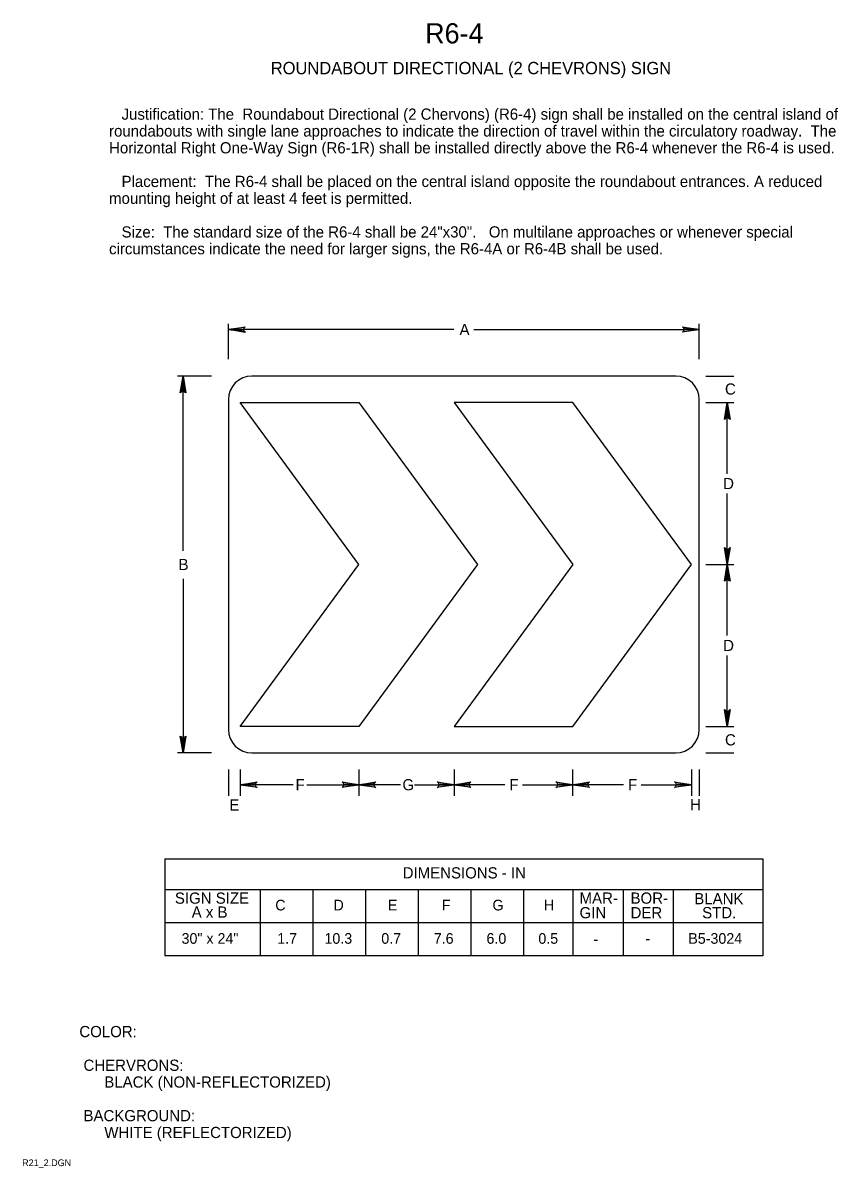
# Model space of a CAD drawing. Extents: x 0.013 to 0.194, y 0.004 to 0.259.
import ezdxf

# ---------------------------------------------------------------- set-up
doc = ezdxf.new("R2010")
doc.units = 0
for name, color, linetype in [('1', 7, 'Continuous'), ('2', 7, 'Continuous'), ('3', 7, 'Continuous')]:
    doc.layers.add(name, color=color, linetype=linetype)

# ---------------------------------------------------------------- blocks, each defined once
blk = doc.blocks.new('RARROW')
at = {"layer": '3'}
for p, q in [((-2.156, 0.285), (-2.2665, 0.384625)), ((-2.2665, 0.384625), (0, 0)), ((0, 0), (-2.2665, -0.379125)), ((-2.156, 0.285), (-2.075625, 0.12075)), ((0, 0), (-2.156, 0.285)), ((-2.14975, -0.2705), (0, 0)), ((-2.075625, 0.12075), (0, 0)), ((0, 0), (-2.074, -0.108)), ((-2.2665, -0.379125), (-2.14975, -0.2705)), ((-2.074, -0.108), (-2.14975, -0.2705))]:
    blk.add_line(p, q, dxfattribs=at)

msp = doc.modelspace()

# ---------------------------------------------------------------- linework, layer by layer
at = {"layer": '3'}
for p, q in [((0.05838, 0.18423), (0.05838, 0.1921)), ((0.16337, 0.18423), (0.16337, 0.1921)), ((0.10867, 0.19085), (0.05838, 0.19085)), ((0.11308, 0.19085), (0.16337, 0.19085)), ((0.05462, 0.18048), (0.047, 0.18048)), ((0.04825, 0.14154), (0.04825, 0.18048)), ((0.15813, 0.18048), (0.06363, 0.18048)), ((0.16487, 0.18048), (0.17112, 0.18048)), ((0.05838, 0.17523), (0.05838, 0.10173)), ((0.08747, 0.13848), (0.061, 0.17457)), ((0.061, 0.17457), (0.08747, 0.17457)), ((0.16337, 0.10173), (0.16337, 0.17523)), ((0.16487, 0.17457), (0.17112, 0.17457)), ((0.16964, 0.15872), (0.16964, 0.17457)), ((0.16964, 0.13848), (0.16964, 0.15432)), ((0.061, 0.10238), (0.08747, 0.13848)), ((0.16487, 0.13848), (0.17112, 0.13848)), ((0.16964, 0.12262), (0.16964, 0.13848)), ((0.04825, 0.13525), (0.04825, 0.09648)), ((0.16964, 0.10238), (0.16964, 0.11823)), ((0.16487, 0.10238), (0.17112, 0.10238)), ((0.05462, 0.09648), (0.047, 0.09648)), ((0.06363, 0.09648), (0.15813, 0.09648)), ((0.16487, 0.09648), (0.17112, 0.09648)), ((0.05838, 0.09278), (0.05838, 0.08695)), ((0.061, 0.09278), (0.061, 0.08695)), ((0.08747, 0.09278), (0.08747, 0.08695)), ((0.10869, 0.09278), (0.10869, 0.08695)), ((0.13516, 0.08695), (0.13516, 0.09278)), ((0.16162, 0.09278), (0.16162, 0.08695)), ((0.16337, 0.09278), (0.16337, 0.08695)), ((0.07283, 0.08939), (0.06112, 0.08939)), ((0.0759, 0.08939), (0.08747, 0.08939)), ((0.09675, 0.08939), (0.08759, 0.08939)), ((0.09984, 0.08939), (0.10869, 0.08939)), ((0.12005, 0.08939), (0.10869, 0.08939)), ((0.12394, 0.08939), (0.13516, 0.08939)), ((0.14652, 0.08939), (0.13516, 0.08939)), ((0.15041, 0.08939), (0.16162, 0.08939)), ((0.04419, 0.07287), (0.17756, 0.07287)), ((0.04419, 0.07287), (0.04419, 0.05125)), ((0.17756, 0.07287), (0.17756, 0.05125)), ((0.17756, 0.066), (0.04419, 0.066)), ((0.06544, 0.066), (0.06544, 0.05125)), ((0.07719, 0.066), (0.07719, 0.05125)), ((0.08894, 0.066), (0.08894, 0.05125)), ((0.10069, 0.066), (0.10069, 0.05125)), ((0.11244, 0.066), (0.11244, 0.05125)), ((0.12419, 0.066), (0.12419, 0.05125)), ((0.12419, 0.066), (0.12419, 0.05262)), ((0.1352, 0.066), (0.1352, 0.05125)), ((0.14644, 0.066), (0.14644, 0.05125)), ((0.15756, 0.066), (0.15756, 0.05125)), ((0.17756, 0.05862), (0.04419, 0.05862)), ((0.17756, 0.05125), (0.04419, 0.05125))]:
    msp.add_line(p, q, dxfattribs=at)
msp.add_lwpolyline([(0.08747, 0.17457), (0.11394, 0.13848), (0.08747, 0.10238), (0.061, 0.10238)], dxfattribs=at)
msp.add_lwpolyline([(0.13516, 0.17457), (0.10869, 0.17457), (0.13516, 0.13848), (0.10869, 0.10238), (0.13516, 0.10238), (0.16162, 0.13848)], close=True, dxfattribs=at)
for centre, start, end in [((0.06363, 0.17523), 90, 180), ((0.15813, 0.17523), 0, 90), ((0.06363, 0.10173), 180, 270), ((0.15813, 0.10173), 270, 0)]:
    msp.add_arc(centre, 0.00525, start, end, dxfattribs=at)

# ---------------------------------------------------------------- block references
at = {"layer": '3', "xscale": 0.0016545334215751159, "yscale": 0.0016366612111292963}
for p, rotation in [((0.05838, 0.19085), 180), ((0.04825, 0.18048), 90), ((0.16964, 0.17457), 90), ((0.16964, 0.13848), -90), ((0.16964, 0.13848), 90), ((0.16964, 0.10238), -90), ((0.04825, 0.09648), -90), ((0.061, 0.08939), 180), ((0.08747, 0.08939), 180), ((0.10869, 0.08939), 180), ((0.13516, 0.08939), 180)]:
    msp.add_blockref('RARROW', p, dxfattribs=dict(at, rotation=rotation))
for p in [(0.16337, 0.19085), (0.08747, 0.08939), (0.10869, 0.08939), (0.13516, 0.08939), (0.16162, 0.08939)]:
    msp.add_blockref('RARROW', p, dxfattribs=at)

# ---------------------------------------------------------------- texts
at = {"layer": '1'}
for s, height, p in [('R6-4', 0.0045, (0.10224, 0.25462)), ('ROUNDABOUT DIRECTIONAL (2 CHEVRONS) SIGN', 0.0027503, (0.06782, 0.24775)), ('COLOR:', 0.0025, (0.02513, 0.03312)), (' CHERVRONS:', 0.0024998, (0.02513, 0.02562)), ('      BLACK (NON-REFLECTORIZED)', 0.0024998, (0.02513, 0.02188)), (' BACKGROUND:', 0.0024998, (0.02513, 0.01438)), ('      WHITE (REFLECTORIZED)', 0.0024998, (0.02513, 0.01063)), ('R21_2.DGN', 0.0015, (0.01238, 0.00438))]:
    msp.add_text(s, height=height, dxfattribs=at).set_placement(p)
at = {"layer": '2'}
for s, height, p in [('   Justification: The  Roundabout Directional (2 Chervons) (R6-4) sign shall be installed on the central island of', 0.00249975, (0.03176, 0.23761)), ('roundabouts with single lane approaches to indicate the direction of travel within the circulatory roadway.  The ', 0.00249975, (0.03176, 0.23386)), ('Horizontal Right One-Way Sign (R6-1R) shall be installed directly above the R6-4 whenever the R6-4 is used.', 0.00249975, (0.03176, 0.23011)), ('   Placement:  The R6-4 shall be placed on the central island opposite the roundabout entrances. A reduced', 0.00249975, (0.03176, 0.22261)), ('mounting height of at least 4 feet is permitted.', 0.0024998, (0.03176, 0.21886)), ('   Size:  The standard size of the R6-4 shall be 24"x30".   On multilane approaches or whenever special ', 0.00249975, (0.03176, 0.21136)), ('circumstances indicate the need for larger signs, the R6-4A or R6-4B shall be used.', 0.0024998, (0.03176, 0.20761))]:
    msp.add_text(s, height=height, dxfattribs=at).set_placement(p)
at = {"layer": '3'}
for s, height, p in [('A', 0.0025, (0.10992, 0.1896)), ('C', 0.0025, (0.16912, 0.17634)), ('D', 0.0025, (0.16871, 0.15527)), ('B', 0.0025, (0.04725, 0.13723)), ('D', 0.0025, (0.16871, 0.11918)), ('C', 0.0025, (0.16912, 0.09814)), ('F', 0.0025, (0.07335, 0.08814)), ('G', 0.0025, (0.09719, 0.08814)), ('F', 0.0025, (0.12104, 0.08814)), ('F', 0.0025, (0.14751, 0.08814)), ('E', 0.0025, (0.05857, 0.08364)), ('H', 0.0025, (0.16136, 0.08371)), ('DIMENSIONS - IN', 0.0024998, (0.09724, 0.0685)), ('SIGN SIZE', 0.0025, (0.04644, 0.06287)), ('MAR-', 0.0025, (0.13669, 0.06287)), ('BOR-', 0.0025, (0.14806, 0.06287)), ('BLANK', 0.0025, (0.16227, 0.06275)), ('A x B', 0.0025, (0.05019, 0.05975)), (' C', 0.002375, (0.06795, 0.06137)), ('D', 0.00238, (0.08181, 0.06137)), ('E', 0.00238, (0.09394, 0.06137)), ('F', 0.00238, (0.10594, 0.06137)), ('G', 0.00238, (0.11727, 0.06137)), ('H', 0.00238, (0.12872, 0.06137)), ('GIN', 0.0025, (0.13669, 0.05962)), ('DER', 0.0025, (0.14806, 0.05962)), ('STD.', 0.0025, (0.16402, 0.05962)), ('30" x 24"', 0.002375, (0.04793, 0.05394)), ('1.7', 0.002375, (0.06927, 0.05394)), ('10.3', 0.002375, (0.0798, 0.05394)), ('0.7', 0.002375, (0.09247, 0.05394)), ('7.6', 0.002375, (0.10418, 0.05394)), ('6.0', 0.002375, (0.11593, 0.05394)), ('0.5', 0.002375, (0.1275, 0.05394)), ('B5-3024', 0.002375, (0.16094, 0.05394)), ('-', 0.00238, (0.13979, 0.05381)), ('-', 0.00238, (0.15138, 0.05394))]:
    msp.add_text(s, height=height, dxfattribs=at).set_placement(p)

doc.saveas('drawing.dxf')
